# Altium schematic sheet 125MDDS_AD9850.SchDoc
size A4
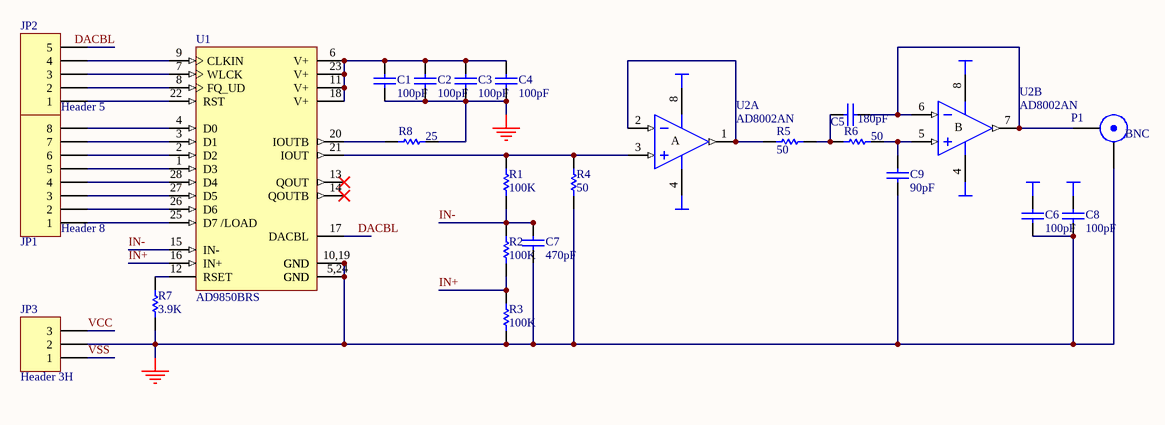
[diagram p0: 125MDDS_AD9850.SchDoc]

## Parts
C1  100pF  [RAD-0.3]
C2  100pF  [RAD-0.3]
C3  100pF  [RAD-0.3]
C4  100pF  [RAD-0.3]
C5  180pF  [RAD-0.3]
C6  100pF  [RAD-0.3]
C7  470pF  [RAD-0.3]
C8  100pF  [RAD-0.3]
C9  90pF  [RAD-0.3]
JP1  Header 8  [HDR1X8]
JP2  Header 5  [HDR1X5]
JP3  Header 3H  [HDR1X3H]
P1  BNC  [BNC_RA CON]
R1  100K  [AXIAL-0.3]
R2  100K  [AXIAL-0.3]
R3  100K  [AXIAL-0.3]
R4  50  [AXIAL-0.3]
R5  50  [AXIAL-0.3]
R6  50  [AXIAL-0.3]
R7  3.9K  [AXIAL-0.3]
R8  25  [AXIAL-0.3]
U1  AD9850BRS  [SSO-G28/E4.3]
U2  AD8002AN  [DIP-8/D11]  (parts A,B of 2)

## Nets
GND: C1.1 C2.1 C3.1 C4.1 C6.1 C7.1 C8.1 C9.1 JP3.2 P1.1(X) R3.1 R4.1 R7.2 R8.2 U1.5(GND) U1.10(GND) U1.19(GND) U1.24(GND)
VCC: C6.2 JP3.3 U2.8(V+)
VSS: C8.2 JP3.1 U2.4(V-)
DACBL: U1.17(DACBL)
IN+: R2.1 R3.2 U1.16(IN+)
IN-: C7.2 R1.1 R2.2 U1.15(IN-)
NetC1_2: C1.2 C2.2 C3.2 C4.2 U1.6(V+) U1.11(V+) U1.18(V+) U1.23(V+)
NetC5_1: C5.1 P1.2(Y) U2.6(IN-) U2.7(OUT)
NetC5_2: C5.2 R5.1 R6.2
NetC9_2: C9.2 R6.1 U2.5(IN+)
NetJP1_1: JP1.1 U1.25(D7_/LOAD)
NetJP1_2: JP1.2 U1.26(D6)
NetJP1_3: JP1.3 U1.27(D5)
NetJP1_4: JP1.4 U1.28(D4)
NetJP1_5: JP1.5 U1.1(D3)
NetJP1_6: JP1.6 U1.2(D2)
NetJP1_7: JP1.7 U1.3(D1)
NetJP1_8: JP1.8 U1.4(D0)
NetJP2_1: JP2.1 U1.22(RST)
NetJP2_2: JP2.2 U1.8(FQ_UD)
NetJP2_3: JP2.3 U1.7(WLCK)
NetJP2_4: JP2.4 U1.9(CLKIN)
NetR1_2: R1.2 R4.2 U1.21(IOUT) U2.3(IN+)
NetR5_2: R5.2 U2.1(OUT) U2.2(IN-)
NetR7_1: R7.1 U1.12(RSET)
NetR8_1: R8.1 U1.20(IOUTB)

Not connected (* = marked no-connect by the designer): JP2 5; U1 13(QOUT)* 14(QOUTB)*

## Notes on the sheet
- Labels drawn without touching a wire or pin: DACBL

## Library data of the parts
C1-C9 = Cap: Capacitor; Manufacturer: Generic Components; Class I: Passive
JP1 = Header 8: Header, 8-Pin; Manufacturer: Generic Components; Class I: Connector
JP2 = Header 5: Header, 5-Pin; Manufacturer: Generic Components; Class I: Connector
JP3 = Header 3H: Header, 3-Pin,  Right Angle; Manufacturer: Generic Components; Class I: Connector
P1 = BNC: BNC Elbow Connector; Manufacturer: Generic Components; Class II: RF Coaxial
R1-R8 = Res1: Resistor; Manufacturer: Generic Components; Class I: Passive
U1 = AD9850BRS: CMOS, 125MHz Complete DDS Synthesizer; Manufacturer: Analog Devices; Package Information: Latest Revision: Rev. A 1997; Class I: RF and IF; Class II: Frequency Synthesiser; Note: Pin 17 is unconnected for optimum performance
U2 = AD8002AN: Dual 600MHz, 50mW Current Feedback Amplifier; Manufacturer: Analog Devices; Revision 1: 10-July-2000: SIM Model Added.; Revision 2: July-2002: Re-released for DXP Platform.; Class II: Operational Amplifier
